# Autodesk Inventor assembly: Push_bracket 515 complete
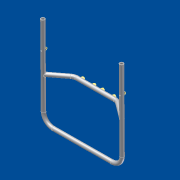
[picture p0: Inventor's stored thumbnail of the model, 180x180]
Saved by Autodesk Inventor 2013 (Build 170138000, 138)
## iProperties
Shininess: 20.0
Length Units: 11269
Angle Units: 11279
Time Units: 11290
Mass Units: 11283
Length Display Precision: 3
Angle Display Precision: 2
Created: 2001-05
Part Number: Push_bracket 515 complete
Document SubType Name: Baugruppe
Designer: dl
Density: 0.0
Volumn: 0.0
Area: 0.0
PropertySet Name: Model Information
Control State: 0
Master: False
Checked Out: False
Author: dl
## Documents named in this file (6)
- C:\Webworld\Webworld2014\ATC2013\Assemblies\ATC-Baby Carriage\SEAT FRAME\Push_bracket 515 complete.iam
- C:\Webworld\Webworld2014\ATC2013\Assemblies\ATC-Baby Carriage\SEAT FRAME\ISO 7049 - ST4.2 x 16 - C - H.ipt
- C:\Webworld\Webworld2014\ATC2013\Assemblies\ATC-Baby Carriage\SEAT FRAME\Clamp_small.ipt
- C:\Webworld\Webworld2014\ATC2013\Assemblies\ATC-Baby Carriage\SEAT FRAME\Rivet 3mm.ipt
- C:\Webworld\Webworld2014\ATC2013\Assemblies\ATC-Baby Carriage\SEAT FRAME\Rubber_block_support.ipt
- C:\Webworld\Webworld2014\ATC2013\Assemblies\ATC-Baby Carriage\SEAT FRAME\Push_bracket 515 welded.ipt
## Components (15 placed, 5 different names)
1. Push_bracket 515 welded:1 — Mate:1, Mate:2, Mate:3, Mate:4, Mate:5, Mate:6, Mate:7, Mate:8, Flush:4, Flush:5, Flush:6
2. Clamp_small:1 — Insert:1, Insert:2, Mate:3, Mate:4, Flush:5
3. Clamp_small:2 — Insert:3, Insert:4, Mate:1, Mate:2, Flush:6
4. Rivet 3mm:1 — Insert:1
5. Rivet 3mm:2 — Insert:2
6. Rivet 3mm:3 — Insert:3
7. Rivet 3mm:4 — Insert:4
8. Rubber_block_support:1 — Mate:5, Flush:1, Flush:2, Flush:3, Flush:4, Insert:8
9. Rubber_block_support:2 — Mate:6, Flush:1, Insert:7
10. Rubber_block_support:3 — Mate:7, Flush:2, Insert:6
11. Rubber_block_support:4 — Mate:8, Flush:3, Insert:5
12. ISO 7049 - ST4.2 x 16 - C - H:1 — Insert:5
13. ISO 7049 - ST4.2 x 16 - C - H:2 — Insert:6
14. ISO 7049 - ST4.2 x 16 - C - H:3 — Insert:7
15. ISO 7049 - ST4.2 x 16 - C - H:4 — Insert:8
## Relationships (22: Insert 8, Mate 8, Flush 6)
- Insert:1: Clamp_small:1 ↔ Rivet 3mm:1
- Insert:2: Clamp_small:1 ↔ Rivet 3mm:2
- Insert:3: Clamp_small:2 ↔ Rivet 3mm:3
- Insert:4: Clamp_small:2 ↔ Rivet 3mm:4
- Mate:1: Push_bracket 515 welded:1 ↔ Clamp_small:2
- Mate:2: Push_bracket 515 welded:1 ↔ Clamp_small:2
- Mate:3: Push_bracket 515 welded:1 ↔ Clamp_small:1
- Mate:4: Push_bracket 515 welded:1 ↔ Clamp_small:1
- Mate:5: Push_bracket 515 welded:1 ↔ Rubber_block_support:1
- Mate:6: Push_bracket 515 welded:1 ↔ Rubber_block_support:2
- Mate:7: Push_bracket 515 welded:1 ↔ Rubber_block_support:3
- Mate:8: Push_bracket 515 welded:1 ↔ Rubber_block_support:4
- Flush:1: Rubber_block_support:1 ↔ Rubber_block_support:2
- Flush:2: Rubber_block_support:1 ↔ Rubber_block_support:3
- Flush:3: Rubber_block_support:1 ↔ Rubber_block_support:4
- Flush:4: Push_bracket 515 welded:1 ↔ Rubber_block_support:1
- Flush:5: Push_bracket 515 welded:1 ↔ Clamp_small:1
- Flush:6: Push_bracket 515 welded:1 ↔ Clamp_small:2
- Insert:5: Rubber_block_support:4 ↔ ISO 7049 - ST4.2 x 16 - C - H:1
- Insert:6: Rubber_block_support:3 ↔ ISO 7049 - ST4.2 x 16 - C - H:2
- Insert:7: Rubber_block_support:2 ↔ ISO 7049 - ST4.2 x 16 - C - H:3
- Insert:8: Rubber_block_support:1 ↔ ISO 7049 - ST4.2 x 16 - C - H:4
